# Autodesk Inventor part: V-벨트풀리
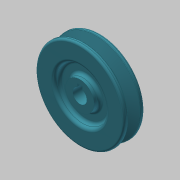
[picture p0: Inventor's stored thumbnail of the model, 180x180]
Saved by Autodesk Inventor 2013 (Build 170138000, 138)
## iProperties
Created: 2019-09
Part Number: V-벨트풀리
Material: 알루미늄 6061
Document SubType Name: Modeling
Designer: mduedu
Density: 2.71 g/cm^3
Mass: 202.898 g
Surface Area: 230.066 cm^2
Volume: 74.8703 cm^3
Author: mduedu
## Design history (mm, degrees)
sketch "스케치1"
  geometry: L1 (-10, 0)-(10, 0); L2 (10, 0)-(10, 43.5); L3 (10, 43.5)-(-10, 43.5); L4 (-10, 43.5)-(-10, 0); L5 (0, 0)-(0, 43.5); L6 (-5.976, 43.5)-(-2.154, 31); L7 (-2.154, 31)-(2.154, 31); L8 (2.154, 31)-(5.976, 43.5); L9 (-10, 39)-(10, 39); 3 further points
  constraints: 18 end point, 8 point on line, 3 perpendicular, 2 midpoint, 2 parallel, 1 coincident, 1 horizontal, 1 other
  dimensions: "d0" = 87 diameter of L3 L1; "d3" = 12.5 distance between parallel lines of L7 L3; "d4" = 34 deg angle of L8 L6; "d5" = 20 distance between parallel lines of L2 L4; "d6" = 8 distance between parallel lines of L9 L7; "d7" = 9.2 distance of point (4.6, 39) point (-4.6, 39)
revolve "회전1" sketch "스케치1" stored, may be unused: angle "d8" = 90 deg
sketch "스케치2"
  geometry: C1 r 14 at (0, 0); C2 r 25 at (0, 0); 1 further point
  constraints: 2 centre point, 2 coincident
  dimensions: "d9" = 28 diameter of C1; "d10" = 50 diameter of C2
extrude "돌출1" cut sketch "스케치2" distance "d11" = 6; taper "d12" = 0 deg
fillet "모깎기1" dims "d13" = 3
fillet "모깎기2" dims "d14" = 3
fillet "모깎기3" dims "d15" = 0.5, "d16" = 1, "d17" = 2
sketch "스케치3"
  geometry: L1 (-2.5, 6.538)-(2.5, 6.538); L2 (2.5, 6.538)-(2.5, 9.3); L3 (2.5, 9.3)-(-2.5, 9.3); L4 (-2.5, 9.3)-(-2.5, 6.538); A1 r 7 centre (0, 0) between (-2.5, 6.538) and (2.5, 6.538); 1 further point
  constraints: 8 end point, 2 parallel, 2 point on circle, 1 centre point, 1 coincident, 1 horizontal, 1 perpendicular
  dimensions: "d18" = 14 diameter of A1; "d20" = 5 distance of L2.end L3.end; "d21" = 16.3 dimension on A1 L3
extrude "돌출2" cut sketch "스케치3" stored distance "d22" = 6; taper "d23" = 0 deg
node "솔리드1"
mirror "대칭1"
